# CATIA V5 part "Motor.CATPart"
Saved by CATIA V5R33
Part number: Motor
Bounding box of the stored display mesh (mm): x -60 to 60, y -30 to 65, z -67.5 to 60
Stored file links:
  D:\PROJECTS\Project 2023\CATIA V5 6R 2023\Resources\Tutorial Files\c12_catia_v5_6r2023_tut\c12Tut1\Motor.CATPart
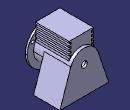
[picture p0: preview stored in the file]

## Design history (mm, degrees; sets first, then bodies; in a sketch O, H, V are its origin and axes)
Body1 (main body)
  Sketch1 on zx-plane, origin (0, 0, 0), H (-1, 0, 0), V (0, 0, 1)
    arc A1 centre (0, 0) radius 35 from (33.1265, 11.2976) to (-33.1265, 11.2976) ccw
    line L1 (-60, -67.5) -> (60, -67.5)
    point P1 (-60, -67.5)
    line L2 (60, -67.5) -> (33.1265, 11.2976)
    line L3 (-60, -67.5) -> (-33.1265, 11.2976)
    point P4 (-33.1265, 11.2976)
    point P5 (-33.1265, 11.2976)
    radius A1 = 35
    length L1 = 120
    distance H L1 = 67.5
    distance P1 V = 60
    horizontal: L1 H
    tangency: L3 A1, L2 A1
    coincidence: L3 P5, P4 A1, P4 P5
  Pad1: profile Sketch1, direction (0, 1, 0), length 65
  Sketch2 on face of Pad1, origin (0, 65, 0), H (-1, 0, 0), V (0, 0, 1)
    circle A1 centre (0, 0) radius 35
    reference projected arc E1 centre (0, 0) radius 35 from (33.1265, 11.2976) to (-33.1265, 11.2976) ccw from edge [face of Pad1 from Sketch1.A1 | end face of Pad1]
    reference projected arc E2 centre (0, 0) radius 35 from (33.1265, 11.2976) to (-33.1265, 11.2976) ccw from edge [face of Pad1 from Sketch1.A1 | end face of Pad1]
    coincidence: A1 E1
    concentricity: A1 E2
  Pad2: profile Sketch2, direction (0, -1, 0), length 90
  Sketch3 on xy-plane, origin (0, 0, 0), H (1, 0, 0), V (0, 1, 0)
    line L1 (-30, 57.5) -> (30, 57.5)
    line L2 (30, 57.5) -> (30, -25)
    line L3 (30, -25) -> (-30, -25)
    line L4 (-30, -25) -> (-30, 57.5)
    reference projected line E1 (-35, -25) -> (35, -25) from edge of Pad2
    reference projected line E2 (33.1265, 65) -> (-33.1265, 65) from edge of Pad1
    length L1 = 60
    distance L4 V = 30
    distance E2 L1 = 7.5
    horizontal: L1 H, L3 H
    vertical: L2 V, L4 V
    coincidence: E1 L3
  Pad3: profile Sketch3, direction (0, 0, 1), length 60
  Sketch4 on face of Pad2, origin (0, -25, 0), H (1, 0, 0), V (0, 0, 1)
    circle A1 centre (0, 0) radius 50
    radius A1 = 50
  Pad4: profile Sketch4, direction (0, -1, 0), length 5
  Sketch5 on face of Pad3, origin (0, 57.5, 0), H (-1, 0, 0), V (0, 0, 1)
    line L1 (-30, 28.8) -> (-25, 28.8)
    line L2 (-25, 28.8) -> (-25, 24.3)
    line L3 (-25, 24.3) -> (-30, 24.3)
    line L4 (-30, 24.3) -> (-30, 28.8)
    reference projected line E1 (-30, 0) -> (-30, 60) from edge of Pad3
    length L1 = 5
    length L2 = 4.5
    distance L3 H = 24.3
    horizontal: L1 H, L3 H
    vertical: L2 V, L4 V
    coincidence: L4 E1
  Pocket1: profile Sketch5, direction (0, -1, 0), up to face of Pad3
  RectPattern1: of Pocket1, direction 1 instances 4, spacing 9, along edge of Pad3 reversed, direction 2 instances 2, spacing 55, along edge of Pad3
  Sketch6 on face of Pad4, origin (0, -30, 0), H (1, 0, 0), V (0, 0, 1)
    circle A1 centre (0, -42.5) radius 3.75
    point P1 (0, -42.5)
    radius A1 = 3.75
    distance P1 H = 42.5
    coincidence: P1 V
  Pocket2: profile Sketch6, direction (0, 1, 0), length 12.7
  CircPattern1: of Pocket2, instances 3, angular step 120, axis from face
  Sketch7 on face of Pad4, origin (0, -30, 0), H (1, 0, 0), V (0, 0, 1)
    circle A1 centre (0, 0) radius 30
    circle A2 centre (0, 0) radius 7.5
    radius A1 = 30
    radius A2 = 7.5
  MultiPocket1: profile Sketch7, domains (length 254; length 90)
